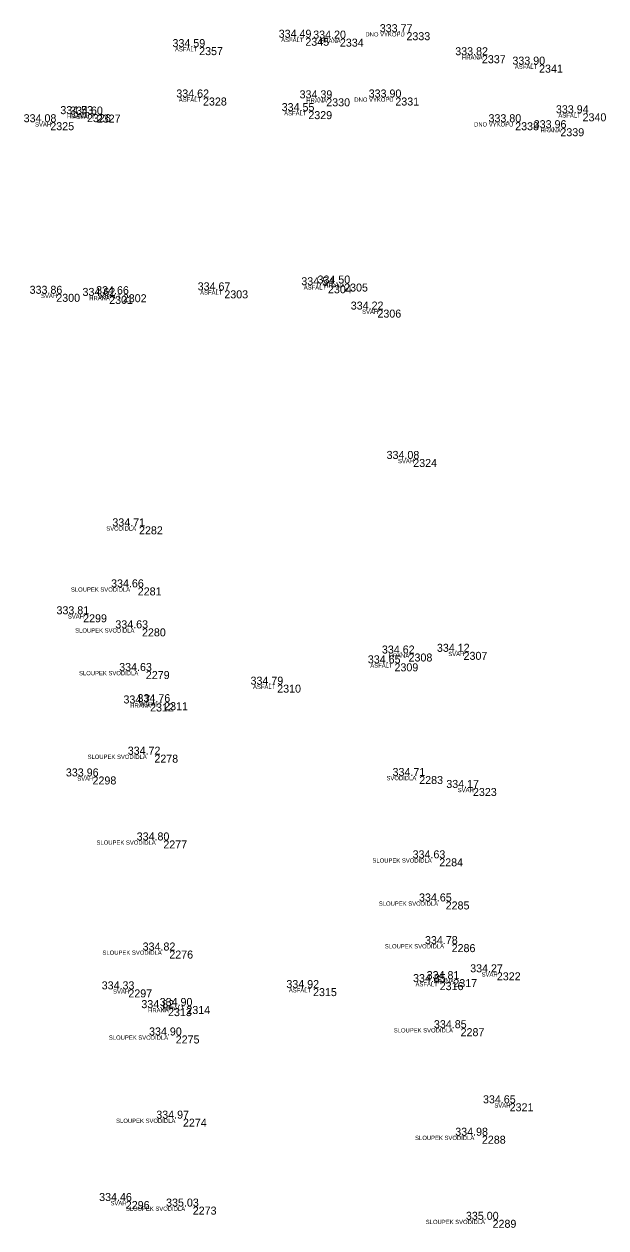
# Model space of a CAD drawing. Extents: x -597865 to -597551, y -1151663 to -1149883.
# Drawn here: x -597666.42 to -597652.77, y -1149965.89 to -1149937.68 of the extents above; entities that cross this region are included whole.
import ezdxf

# ---------------------------------------------------------------- set-up
doc = ezdxf.new("R2010")
doc.units = 0
for name, color, linetype in [('Vrstva 11', 7, 'Continuous'), ('Vrstva 12', 7, 'Continuous'), ('Vrstva 13', 7, 'Continuous'), ('Vrstva 14', 7, 'Continuous')]:
    doc.layers.add(name, color=color, linetype=linetype)

msp = doc.modelspace()

# ---------------------------------------------------------------- linework, layer by layer
at = {"layer": 'Vrstva 11'}
for p, q in [((-597659.82, -1149938), (-597659.82, -1149938)), ((-597659.01, -1149938.02), (-597659.01, -1149938.02)), ((-597657.45, -1149937.87), (-597657.45, -1149937.87)), ((-597662.31, -1149938.22), (-597662.31, -1149938.22)), ((-597655.68, -1149938.41), (-597655.68, -1149938.41)), ((-597654.34, -1149938.63), (-597654.34, -1149938.63)), ((-597662.22, -1149939.4), (-597662.22, -1149939.4)), ((-597659.33, -1149939.42), (-597659.33, -1149939.42)), ((-597657.71, -1149939.4), (-597657.71, -1149939.4)), ((-597665.8, -1149939.98), (-597665.8, -1149939.98)), ((-597664.94, -1149939.79), (-597664.94, -1149939.79)), ((-597664.71, -1149939.8), (-597664.71, -1149939.8)), ((-597659.75, -1149939.72), (-597659.75, -1149939.72)), ((-597654.9, -1149939.98), (-597654.9, -1149939.98)), ((-597653.32, -1149939.77), (-597653.32, -1149939.77)), ((-597653.84, -1149940.12), (-597653.84, -1149940.12)), ((-597661.72, -1149943.92), (-597661.72, -1149943.92)), ((-597659.29, -1149943.8), (-597659.29, -1149943.8)), ((-597658.91, -1149943.76), (-597658.91, -1149943.76)), ((-597665.66, -1149944), (-597665.66, -1149944)), ((-597664.42, -1149944.05), (-597664.42, -1149944.05)), ((-597664.1, -1149944.01), (-597664.1, -1149944.01)), ((-597658.13, -1149944.37), (-597658.13, -1149944.37)), ((-597657.29, -1149947.87), (-597657.29, -1149947.87)), ((-597663.72, -1149949.45), (-597663.72, -1149949.45)), ((-597663.75, -1149950.88), (-597663.75, -1149950.88)), ((-597665.03, -1149951.51), (-597665.03, -1149951.51)), ((-597663.65, -1149951.84), (-597663.65, -1149951.84)), ((-597656.11, -1149952.39), (-597656.11, -1149952.39)), ((-597657.73, -1149952.66), (-597657.73, -1149952.66)), ((-597657.4, -1149952.43), (-597657.4, -1149952.43)), ((-597663.56, -1149952.84), (-597663.56, -1149952.84)), ((-597660.48, -1149953.16), (-597660.48, -1149953.16)), ((-597663.46, -1149953.6), (-597663.46, -1149953.6)), ((-597663.13, -1149953.57), (-597663.13, -1149953.57)), ((-597663.36, -1149954.8), (-597663.36, -1149954.8)), ((-597664.81, -1149955.31), (-597664.81, -1149955.31)), ((-597657.15, -1149955.3), (-597657.15, -1149955.3)), ((-597655.89, -1149955.58), (-597655.89, -1149955.58)), ((-597663.15, -1149956.81), (-597663.15, -1149956.81)), ((-597656.68, -1149957.23), (-597656.68, -1149957.23)), ((-597656.53, -1149958.24), (-597656.53, -1149958.24)), ((-597663.01, -1149959.39), (-597663.01, -1149959.39)), ((-597656.39, -1149959.24), (-597656.39, -1149959.24)), ((-597655.33, -1149959.9), (-597655.33, -1149959.9)), ((-597663.97, -1149960.3), (-597663.97, -1149960.3)), ((-597659.64, -1149960.27), (-597659.64, -1149960.27)), ((-597656.67, -1149960.13), (-597656.67, -1149960.13)), ((-597656.35, -1149960.06), (-597656.35, -1149960.06)), ((-597663.04, -1149960.74), (-597663.04, -1149960.74)), ((-597662.61, -1149960.69), (-597662.61, -1149960.69)), ((-597662.86, -1149961.38), (-597662.86, -1149961.38)), ((-597656.18, -1149961.21), (-597656.18, -1149961.21)), ((-597655.03, -1149962.97), (-597655.03, -1149962.97)), ((-597662.69, -1149963.33), (-597662.69, -1149963.33)), ((-597655.68, -1149963.73), (-597655.68, -1149963.73)), ((-597664.03, -1149965.26), (-597664.03, -1149965.26)), ((-597662.46, -1149965.39), (-597662.46, -1149965.39)), ((-597655.43, -1149965.7), (-597655.43, -1149965.7))]:
    msp.add_line(p, q, dxfattribs=at)

# ---------------------------------------------------------------- texts
at = {"layer": 'Vrstva 12'}
for s, p in [('333.77 ', (-597658.075, -1149937.87)), ('334.49 ', (-597660.445, -1149938)), ('334.20 ', (-597659.635, -1149938.02)), ('334.59 ', (-597662.935, -1149938.22)), ('333.82 ', (-597656.305, -1149938.41)), ('333.90 ', (-597654.965, -1149938.63)), ('334.62 ', (-597662.845, -1149939.4)), ('334.39 ', (-597659.955, -1149939.42)), ('333.90 ', (-597658.335, -1149939.4)), ('334.53 ', (-597665.565, -1149939.79)), ('334.60 ', (-597665.335, -1149939.8)), ('334.55 ', (-597660.375, -1149939.72)), ('333.94 ', (-597653.945, -1149939.77)), ('334.08 ', (-597666.425, -1149939.98)), ('333.80 ', (-597655.525, -1149939.98)), ('333.96 ', (-597654.465, -1149940.12)), ('334.54 ', (-597659.915, -1149943.8)), ('334.50 ', (-597659.535, -1149943.76)), ('333.86 ', (-597666.285, -1149944)), ('334.62 ', (-597665.045, -1149944.05)), ('334.66 ', (-597664.725, -1149944.01)), ('334.67 ', (-597662.345, -1149943.92)), ('334.22 ', (-597658.755, -1149944.37)), ('334.08 ', (-597657.915, -1149947.87)), ('334.71 ', (-597664.345, -1149949.45)), ('334.66 ', (-597664.375, -1149950.88)), ('333.81 ', (-597665.655, -1149951.51)), ('334.63 ', (-597664.275, -1149951.84)), ('334.62 ', (-597658.025, -1149952.43)), ('334.12 ', (-597656.735, -1149952.39)), ('334.63 ', (-597664.185, -1149952.84)), ('334.65 ', (-597658.355, -1149952.66)), ('334.79 ', (-597661.105, -1149953.16)), ('334.71 ', (-597664.085, -1149953.6)), ('334.76 ', (-597663.755, -1149953.57)), ('334.72 ', (-597663.985, -1149954.8)), ('333.96 ', (-597665.435, -1149955.31)), ('334.71 ', (-597657.775, -1149955.3)), ('334.17 ', (-597656.515, -1149955.58)), ('334.80 ', (-597663.775, -1149956.81)), ('334.63 ', (-597657.305, -1149957.23)), ('334.65 ', (-597657.155, -1149958.24)), ('334.78 ', (-597657.015, -1149959.24)), ('334.82 ', (-597663.635, -1149959.39)), ('334.27 ', (-597655.955, -1149959.9)), ('334.85 ', (-597657.295, -1149960.13)), ('334.81 ', (-597656.975, -1149960.06)), ('334.33 ', (-597664.595, -1149960.3)), ('334.92 ', (-597660.265, -1149960.27)), ('334.82 ', (-597663.665, -1149960.74)), ('334.90 ', (-597663.235, -1149960.69)), ('334.85 ', (-597656.805, -1149961.21)), ('334.90 ', (-597663.485, -1149961.38)), ('334.65 ', (-597655.655, -1149962.97)), ('334.97 ', (-597663.315, -1149963.33)), ('334.98 ', (-597656.305, -1149963.73)), ('334.46 ', (-597664.655, -1149965.26)), ('335.03 ', (-597663.085, -1149965.39)), ('335.00 ', (-597656.055, -1149965.7))]:
    msp.add_text(s, height=0.1875, dxfattribs=at).set_placement(p)
at = {"layer": 'Vrstva 13'}
for s, p in [('2345', (-597659.82, -1149938.188)), ('2334', (-597659.01, -1149938.208)), ('2333', (-597657.45, -1149938.058)), ('2357', (-597662.31, -1149938.407)), ('2337', (-597655.68, -1149938.597)), ('2341', (-597654.34, -1149938.818)), ('2328', (-597662.22, -1149939.588)), ('2330', (-597659.33, -1149939.607)), ('2331', (-597657.71, -1149939.588)), ('2325', (-597665.8, -1149940.167)), ('2326', (-597664.94, -1149939.978)), ('2327', (-597664.71, -1149939.988)), ('2329', (-597659.75, -1149939.907)), ('2338', (-597654.9, -1149940.167)), ('2340', (-597653.32, -1149939.958)), ('2339', (-597653.84, -1149940.308)), ('2303', (-597661.72, -1149944.107)), ('2304', (-597659.29, -1149943.988)), ('2305', (-597658.91, -1149943.948)), ('2300', (-597665.66, -1149944.188)), ('2301', (-597664.42, -1149944.238)), ('2302', (-597664.1, -1149944.198)), ('2306', (-597658.13, -1149944.558)), ('2324', (-597657.29, -1149948.058)), ('2282', (-597663.72, -1149949.637)), ('2281', (-597663.75, -1149951.068)), ('2299', (-597665.03, -1149951.698)), ('2280', (-597663.65, -1149952.028)), ('2307', (-597656.11, -1149952.578)), ('2309', (-597657.73, -1149952.847)), ('2308', (-597657.4, -1149952.617)), ('2279', (-597663.56, -1149953.028)), ('2310', (-597660.48, -1149953.347)), ('2312', (-597663.46, -1149953.788)), ('2311', (-597663.13, -1149953.758)), ('2278', (-597663.36, -1149954.988)), ('2298', (-597664.81, -1149955.498)), ('2283', (-597657.15, -1149955.488)), ('2323', (-597655.89, -1149955.768)), ('2277', (-597663.15, -1149956.998)), ('2284', (-597656.68, -1149957.417)), ('2285', (-597656.53, -1149958.427)), ('2276', (-597663.01, -1149959.578)), ('2286', (-597656.39, -1149959.427)), ('2322', (-597655.33, -1149960.088)), ('2297', (-597663.97, -1149960.488)), ('2315', (-597659.64, -1149960.458)), ('2316', (-597656.67, -1149960.318)), ('2317', (-597656.35, -1149960.248)), ('2313', (-597663.04, -1149960.927)), ('2314', (-597662.61, -1149960.877)), ('2275', (-597662.86, -1149961.568)), ('2287', (-597656.18, -1149961.397)), ('2321', (-597655.03, -1149963.157)), ('2274', (-597662.69, -1149963.518)), ('2288', (-597655.68, -1149963.917)), ('2296', (-597664.03, -1149965.448)), ('2273', (-597662.46, -1149965.578)), ('2289', (-597655.43, -1149965.887))]:
    msp.add_text(s, height=0.1875, dxfattribs=at).set_placement(p)
at = {"layer": 'Vrstva 14'}
for s, p in [('ASFALT', (-597660.387, -1149938.1)), ('HRANA', (-597659.477, -1149938.12)), ('DNO VYKOPU', (-597658.412, -1149937.97)), ('ASFALT', (-597662.877, -1149938.32)), ('HRANA', (-597656.147, -1149938.51)), ('ASFALT', (-597654.907, -1149938.73)), ('ASFALT', (-597662.787, -1149939.5)), ('HRANA', (-597659.797, -1149939.52)), ('DNO VYKOPU', (-597658.672, -1149939.5)), ('SVAH', (-597666.158, -1149940.08)), ('HRANA', (-597665.407, -1149939.89)), ('ASFALT', (-597665.277, -1149939.9)), ('ASFALT', (-597660.317, -1149939.82)), ('DNO VYKOPU', (-597655.863, -1149940.08)), ('ASFALT', (-597653.887, -1149939.87)), ('HRANA', (-597654.307, -1149940.22)), ('ASFALT', (-597662.287, -1149944.02)), ('ASFALT', (-597659.857, -1149943.9)), ('HRANA', (-597659.377, -1149943.86)), ('SVAH', (-597666.018, -1149944.1)), ('HRANA', (-597664.887, -1149944.15)), ('ASFALT', (-597664.667, -1149944.11)), ('SVAH', (-597658.488, -1149944.47)), ('SVAH', (-597657.648, -1149947.97)), ('SVODIDLA', (-597664.487, -1149949.55)), ('SLOUPEK SVODIDLA', (-597665.317, -1149950.98)), ('SVAH', (-597665.388, -1149951.61)), ('SLOUPEK SVODIDLA', (-597665.217, -1149951.94)), ('SVAH', (-597656.468, -1149952.49)), ('ASFALT', (-597658.297, -1149952.76)), ('HRANA', (-597657.867, -1149952.53)), ('SLOUPEK SVODIDLA', (-597665.127, -1149952.94)), ('ASFALT', (-597661.047, -1149953.26)), ('HRANA', (-597663.927, -1149953.7)), ('ASFALT', (-597663.697, -1149953.67)), ('SLOUPEK SVODIDLA', (-597664.927, -1149954.9)), ('SVAH', (-597665.168, -1149955.41)), ('SVODIDLA', (-597657.917, -1149955.4)), ('SVAH', (-597656.248, -1149955.68)), ('SLOUPEK SVODIDLA', (-597664.717, -1149956.91)), ('SLOUPEK SVODIDLA', (-597658.247, -1149957.33)), ('SLOUPEK SVODIDLA', (-597658.097, -1149958.34)), ('SLOUPEK SVODIDLA', (-597664.577, -1149959.49)), ('SLOUPEK SVODIDLA', (-597657.957, -1149959.34)), ('SVAH', (-597655.688, -1149960)), ('SVAH', (-597664.328, -1149960.4)), ('ASFALT', (-597660.207, -1149960.37)), ('ASFALT', (-597657.237, -1149960.23)), ('HRANA', (-597656.817, -1149960.16)), ('HRANA', (-597663.507, -1149960.84)), ('ASFALT', (-597663.177, -1149960.79)), ('SLOUPEK SVODIDLA', (-597664.427, -1149961.48)), ('SLOUPEK SVODIDLA', (-597657.747, -1149961.31)), ('SVAH', (-597655.388, -1149963.07)), ('SLOUPEK SVODIDLA', (-597664.257, -1149963.43)), ('SLOUPEK SVODIDLA', (-597657.247, -1149963.83)), ('SVAH', (-597664.388, -1149965.36)), ('SLOUPEK SVODIDLA', (-597664.027, -1149965.49)), ('SLOUPEK SVODIDLA', (-597656.997, -1149965.8))]:
    msp.add_text(s, height=0.1, dxfattribs=at).set_placement(p)

doc.saveas('drawing.dxf')
